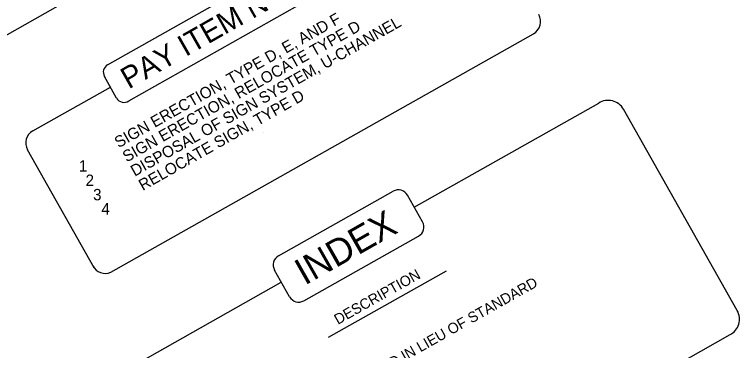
# Model space of a CAD drawing. Extents: x 2217708 to 2219063, y 217550 to 219141.
# Drawn here: x 2218552.8 to 2219010.8, y 218258.3 to 218470.7 of the extents above; entities that cross this region are included whole.
import ezdxf

# ---------------------------------------------------------------- set-up
doc = ezdxf.new("R2010")
doc.units = 0
for name, color, linetype in [('Default', 7, 'Continuous'), ('Sheet Plot Border Inside CELL', 7, 'Continuous'), ('Sheet Title CELL', 7, 'Continuous')]:
    doc.layers.add(name, color=color, linetype=linetype)

msp = doc.modelspace()

# ---------------------------------------------------------------- linework, layer by layer
at = {"layer": 'Default'}
msp.add_line((2218751.18, 218266.74), (2218825.62, 218308.79), dxfattribs=at)
at = {"layer": 'Sheet Plot Border Inside CELL'}
msp.add_line((2218709.86, 218396.37), (2218709.86, 218396.37), dxfattribs=at)
at = {"layer": 'Sheet Title CELL'}
for p, q in [((2218517.9, 218441), (2218819.79, 218611.5)), ((2218613.58, 218307.88), (2218880.61, 218458.61)), ((2218617.33, 218417.89), (2218609.61, 218431.56)), ((2218564.45, 218397.26), (2218613.38, 218424.89)), ((2218805.29, 218348.95), (2218921.89, 218414.71)), ((2219009.35, 218283.56), (2218937.45, 218410.89)), ((2218603.21, 218310.55), (2218561.08, 218385.12)), ((2218810.56, 218339.63), (2218801.02, 218356.52)), ((2218726.61, 218292.25), (2218717.07, 218309.14)), ((2218604.47, 218235.5), (2218721.37, 218301.53)), ((2218687.19, 218089.02), (2219004.87, 218268.4))]:
    msp.add_line(p, q, dxfattribs=at)
for points in [[(2218611.64, 218438.85), (2218767.79, 218527.13)], [(2218624.96, 218416.07), (2218781.11, 218504.36)], [(2218719.57, 218318.13), (2218792.03, 218359.02)], [(2218735.6, 218289.75), (2218808.06, 218330.64)]]:
    msp.add_lwpolyline(points, dxfattribs=at)
for centre, radius, start, end in [((2218876.23, 218466.37), 8.91, 299.4569, 29.4569), ((2218614.26, 218434.19), 5.34, 119.4569, 209.4569), ((2218621.99, 218420.52), 5.34, 209.4569, 303.7349), ((2218927.87, 218405.48), 11, 29.4569, 122.9586), ((2218568.83, 218389.51), 8.91, 119.4569, 209.4569), ((2218795.27, 218353.27), 6.6, 29.4569, 119.4569), ((2218804.81, 218336.39), 6.6, 299.4569, 29.4569), ((2218722.82, 218312.39), 6.6, 119.4569, 209.4569), ((2218609.99, 218315.42), 8.35, 205.4831, 295.4831), ((2218732.36, 218295.5), 6.6, 209.4569, 299.4569), ((2218999.77, 218278.15), 11, 297.5767, 29.4569)]:
    msp.add_arc(centre, radius, start, end, dxfattribs=at)

# ---------------------------------------------------------------- texts
at = {"layer": 'Default'}
for s, height, rotation, p in [('INDEX', 16.783, 29.6392, (2218736.19, 218299.27)), ('DESCRIPTION', 6.6381, 29.4569, (2218757.11, 218274.49)), ('SIGN-2             DETAIL TO BE USED IN LIEU OF STANDARD', 6.6381, 29.4569, (2218667.52, 218177.08))]:
    msp.add_text(s, height=height, rotation=rotation, dxfattribs=at).set_placement(p)
at = {"layer": 'Sheet Title CELL'}
for s, height, rotation, p in [('PAY ITEM NOTES', 13.5912, 29.6392, (2218624.95, 218423.33)), ('SIGN ERECTION, TYPE D, E, AND F', 7.1994, 29.4835, (2218618.56, 218386.14)), ('SIGN ERECTION, RELOCATE TYPE D', 7.1994, 29.4835, (2218623.66, 218377.14)), ('DISPOSAL OF SIGN SYSTEM, U-CHANNEL', 7.1994, 29.4835, (2218628.75, 218368.13)), ('RELOCATE SIGN, TYPE D', 7.1994, 29.4835, (2218633.84, 218359.12)), ('1', 7.2, 0.0229, (2218593.47, 218371.41)), ('2', 7.2, 0.0229, (2218597.72, 218362.34)), ('3', 7.2, 0.0229, (2218602.45, 218353.28)), ('4', 7.2, 0.0229, (2218607.69, 218344.31))]:
    msp.add_text(s, height=height, rotation=rotation, dxfattribs=at).set_placement(p)

doc.saveas('drawing.dxf')
